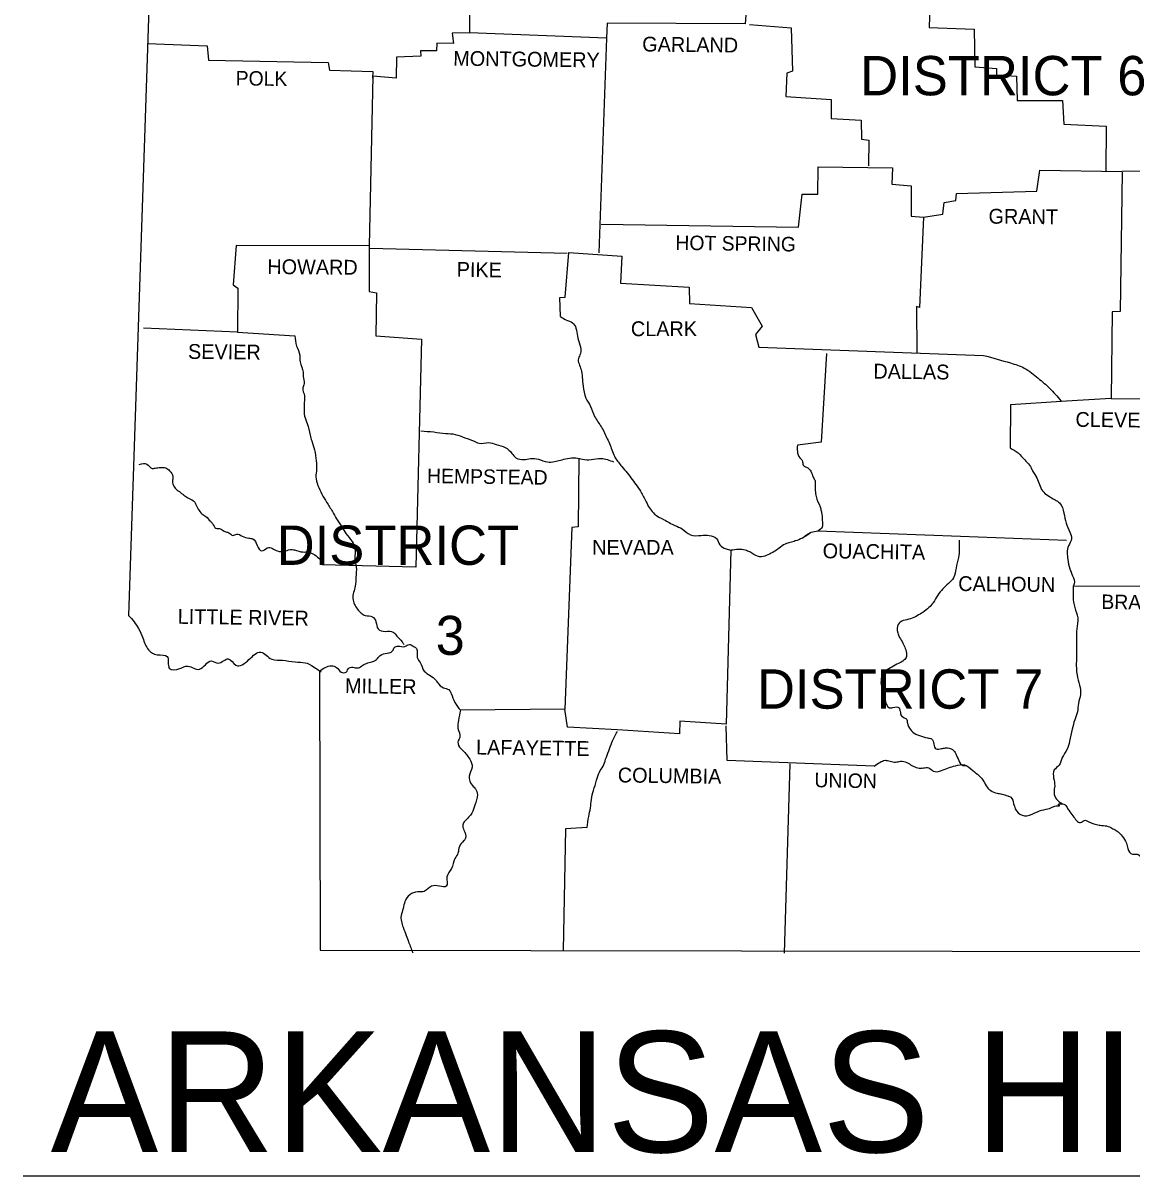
# Model space of a CAD drawing. Extents: x -33639 to 34530, y -17264 to 5867.
# Drawn here: x 1228 to 2998, y -10461 to -8621 of the extents above; entities that cross this region are included whole.
import ezdxf

# ---------------------------------------------------------------- set-up
doc = ezdxf.new("R2010")
doc.units = 0
for name, color, linetype in [('1', 7, 'Continuous'), ('2', 7, 'Continuous'), ('3', 7, 'Continuous')]:
    doc.layers.add(name, color=color, linetype=linetype)

msp = doc.modelspace()

# ---------------------------------------------------------------- linework, layer by layer
at = {"layer": '1'}
msp.add_line((1228.1, -10460.7), (4815.5, -10460.7), dxfattribs=at)
for points in [[(1332.2, -7158.5), (1446.1, -8073.2), (1396.6, -9566.3)], [(1941.4, -8314.8), (1940.3, -8636.8), (1912.8, -8637.3), (1915, -8653.9), (1888.6, -8653.3), (1888, -8665.4), (1862.2, -8665.4), (1862.7, -8674.2), (1824.2, -8675.3), (1823.6, -8708.9), (1786.2, -8705.6), (1780.2, -8976.4), (1568.3, -8975.8), (1563.3, -9038.6), (1571, -9044.1), (1570.5, -9114.5), (1420.2, -9107.9)], [(2565.5, -8557), (2385.5, -8551.5), (2380.6, -8622.5), (2160.4, -8621.4), (2159.3, -8645.1)], [(2614.5, -8555.3), (2676.1, -8559.2), (2673.9, -8628), (2746, -8630.7), (2747.1, -8690.7), (2781.2, -8693.5), (2781.2, -8703.9), (2813.2, -8706.1), (2814.3, -8744.7), (2886.9, -8744.7), (2889.1, -8782.6), (2956.3, -8785.9), (2955.7, -8857.5)], [(2387.2, -8623.6), (2453.8, -8628.5), (2456, -8697.9), (2446.6, -8701.2), (2445.5, -8738.1), (2517.6, -8743), (2517.6, -8773.3), (2565.5, -8776), (2566.1, -8806.3), (2577.6, -8808), (2577.1, -8848.7)], [(2159.3, -8645.1), (1940.3, -8636.8)], [(2159.3, -8645.1), (2146.7, -8987.9)], [(1426.8, -8653.9), (1522, -8657.2), (1524.2, -8680.3), (1714.7, -8684.1), (1716.9, -8696.2), (1786.2, -8698.4), (1785.7, -8708.9)], [(3612.3, -8794.2), (3404.2, -8788.7), (3403.1, -8856.4), (2982.1, -8858)], [(2150.5, -8942.2), (2465.3, -8946.6), (2471.4, -8894.4), (2496.2, -8894.4), (2496.7, -8850.3), (2615.6, -8852), (2614.5, -8878.4), (2645.3, -8880.6), (2645.3, -8929), (2665.1, -8930.7)], [(2665.1, -8930.7), (2695.9, -8926.3), (2698.1, -8907.6), (2716.3, -8904.3), (2717.4, -8893.3), (2845.6, -8889.4), (2850.6, -8855.8), (2982.1, -8858)], [(2982.1, -8859.1), (2978.8, -9081.5), (2966.2, -9082), (2964.5, -9220.2)], [(2665.1, -8930.7), (2658.5, -9074.9), (2653.6, -9073.2), (2654.1, -9148.1)], [(1780.2, -8976.4), (1780.2, -9049.6), (1792.3, -9051.8), (1791.2, -9120), (1863.8, -9125.5), (1855, -9489.3), (1705.3, -9485.4)], [(1781.3, -8980.2), (2096.1, -8988.5)], [(2085.6, -9089.2), (2084.5, -9058.9), (2093.3, -9058.4), (2098.8, -8987.4), (2183.6, -8992.9), (2181.4, -9036.4), (2290.9, -9042.4), (2291.4, -9068.8), (2390.5, -9074.9), (2407.6, -9104.6), (2397.1, -9117.8), (2402.1, -9138.2), (2760.9, -9151.4)], [(1570.5, -9114.5), (1661.8, -9120)], [(2509.9, -9148.6), (2501.7, -9290.1), (2463.7, -9294.5)], [(2885.3, -9225.1), (2803.8, -9230.1), (2803.3, -9298.9)], [(2964.5, -9220.2), (2884.2, -9225.1)], [(2964.5, -9220.2), (3159.3, -9221.3)], [(2114.8, -9315.4), (2113.7, -9424.9), (2103.8, -9426), (2092.8, -9716)], [(2496.2, -9431.5), (2724, -9439.8), (2893, -9446.4)], [(2357.5, -9462.3), (2350.3, -9739.7), (2276, -9734.8), (2275.5, -9755.1), (2176.4, -9749.1)], [(2904, -9519.6), (3152.7, -9519)], [(1700.9, -9655), (1702, -10100.2), (3719, -10103.5)], [(2176.4, -9749.1), (2096.6, -9744.7), (2092.8, -9716), (1926, -9717.7)], [(2586.4, -9806.9), (2351.4, -9798), (2350.3, -9742.5)], [(2451.6, -9803), (2442.8, -10105.1)], [(2128, -9904.8), (2093.9, -9907), (2090, -10100.7)]]:
    msp.add_lwpolyline(points, dxfattribs=at)
for points in [[(2085.6, -9089.2), (2094.4, -9094.7), (2104.9, -9099.6), (2110.4, -9107.9), (2112.6, -9120.6), (2116.4, -9134.3), (2117.5, -9148.6), (2114.2, -9156.3), (2118.6, -9173.9), (2120.3, -9186.1), (2121.9, -9200.4), (2126.3, -9219.6), (2133.5, -9232.8), (2140.1, -9248.8), (2151.1, -9265.9), (2160.4, -9284.6), (2164.8, -9294.5), (2173.1, -9314.8), (2183.6, -9328.6), (2200.1, -9349.5), (2214.9, -9371), (2223.2, -9386.9), (2235.8, -9404.5), (2250.2, -9413.3), (2268.3, -9422.7), (2279.9, -9428.2), (2293.1, -9437.6), (2310.1, -9438.7), (2322.8, -9438.7), (2334.4, -9443.6), (2339.9, -9453.5), (2349.8, -9460.1), (2357.5, -9462.3)], [(1661.8, -9120), (1664.6, -9136.5), (1669.5, -9150.8), (1670.1, -9161.8), (1675, -9178.3), (1675, -9184.4), (1676.7, -9196.5), (1674.5, -9203.1), (1677.2, -9216.3), (1676.7, -9226.2), (1676.7, -9234.5), (1677.2, -9248.2), (1681.6, -9260.3), (1686, -9278.5), (1688.8, -9287.9), (1693.2, -9302.2), (1695.9, -9319.8), (1696.5, -9333), (1695.4, -9345.1), (1698.7, -9358.9), (1704.8, -9372.6), (1712.5, -9385.8), (1721.8, -9400.7), (1728.4, -9412.2), (1736.7, -9424.9), (1743.3, -9435.4), (1753.2, -9448.6), (1757.6, -9459.6), (1757.6, -9475), (1759.8, -9489.3), (1759.2, -9505.3), (1758.1, -9519.6), (1754.3, -9539.4), (1757, -9548.7), (1767.5, -9562.5), (1774.1, -9566.3), (1785.7, -9568.5), (1791.2, -9576.3), (1794.5, -9587.8), (1806, -9591.7), (1818.7, -9592.8), (1824.7, -9599.4), (1833, -9608.2), (1835.7, -9612.6)], [(2760.9, -9151.4), (2803.8, -9163.5), (2825.8, -9171.7), (2847.8, -9187.7), (2866, -9203.7), (2884.2, -9224)], [(1862.7, -9271.9), (1883.6, -9273.6), (1902.9, -9275.8), (1917.7, -9277.4), (1933.2, -9282.9), (1946.9, -9287.9), (1955.7, -9291.7), (1970.6, -9290.6), (1983.2, -9293.4), (1997.5, -9298.3), (2008, -9307.7), (2014.6, -9314.8), (2027.3, -9317.6), (2037.7, -9315.9), (2050.4, -9317), (2064.7, -9321.4), (2076.2, -9320.9), (2085.6, -9318.7), (2096.6, -9315.9), (2110.4, -9314.8), (2120.8, -9317), (2134.6, -9317.6), (2150.5, -9315.9), (2170.4, -9321.4)], [(2463.7, -9294.5), (2463.7, -9304.9), (2467.5, -9314.8), (2471.4, -9319.2), (2473, -9326.4), (2478, -9329.7), (2485.2, -9336.3), (2489, -9345.7), (2491.8, -9351.7), (2491.8, -9359.4), (2492.3, -9367.1), (2493.4, -9376.5), (2500, -9393), (2501.7, -9399.6), (2502.8, -9405.1), (2503.3, -9414.4), (2503.3, -9425.5), (2496.2, -9431.5)], [(2803.3, -9298.9), (2815.9, -9307.1), (2826.4, -9318.1), (2834.1, -9326.4), (2839, -9335.7), (2845.6, -9346.8), (2855, -9367.7), (2863.2, -9374.8), (2874.8, -9382), (2882, -9386.9), (2889.1, -9402.9), (2892.4, -9418.9), (2898.5, -9433.2), (2901.2, -9444.2), (2896.3, -9455.2), (2895.2, -9477.2), (2898.5, -9492), (2902.9, -9503.1), (2905.6, -9515.7), (2904, -9519.6)], [(1413.6, -9325.3), (1425.7, -9324.7), (1434, -9331.9), (1438.9, -9331.3), (1447.7, -9330.2), (1456, -9330.8), (1462, -9335.7), (1467, -9344.6), (1466.5, -9352.8), (1467, -9356.1), (1470.9, -9363.3), (1477.5, -9368.8), (1484.6, -9374.3), (1491.2, -9378.7), (1502.2, -9385.8), (1503.3, -9388), (1507.7, -9396.8), (1513.2, -9404), (1519.8, -9408.4), (1527, -9416.1), (1530.3, -9419.4), (1535.8, -9427.1), (1541.8, -9427.7), (1550.1, -9432.6), (1556.2, -9434.3), (1562.8, -9438.7), (1569.4, -9436.5), (1577.6, -9439.8), (1588.6, -9443.1), (1594.7, -9444.2), (1601.8, -9454.6), (1609, -9463.4), (1617.8, -9458.5), (1634.3, -9463.4), (1644.8, -9464), (1654.1, -9461.2), (1661.3, -9461.8), (1674.5, -9465.1), (1682.7, -9465.1), (1691.5, -9468.4), (1699.8, -9475), (1705.3, -9482.1), (1705.3, -9485.4)], [(2485.7, -9433.7), (2471.4, -9443.1), (2460.4, -9447.5), (2452.1, -9450.2), (2444.4, -9452.4), (2434.5, -9459), (2426.8, -9464.5), (2416.4, -9469.5), (2406.5, -9472.8), (2394.3, -9468.9), (2387.7, -9465.1), (2380.6, -9462.3), (2357.5, -9462.3)], [(2471.4, -9443.1), (2485.7, -9433.7), (2496.2, -9431.5)], [(2721.8, -9446.4), (2720.7, -9473.9), (2716.9, -9490.9), (2713, -9506.4), (2704.7, -9515.2), (2695.9, -9524), (2687.7, -9533.9), (2680.5, -9546), (2673.4, -9553.7), (2664, -9561.4), (2654.7, -9566.9), (2644.2, -9571.8), (2632.7, -9574.6), (2624.4, -9580.7), (2623.8, -9593.9), (2633.2, -9612.6), (2636.5, -9621.4), (2637.6, -9631.8), (2633.8, -9637.9), (2624.9, -9642.8), (2614.5, -9648.9), (2605.1, -9654.4), (2598.5, -9663.8), (2597.4, -9676.4), (2601.8, -9691.3), (2603.5, -9700.1), (2610.6, -9713.8), (2616.1, -9713.3), (2626, -9713.8), (2627.1, -9716.6), (2627.7, -9719.3), (2629.9, -9726.5), (2638.2, -9732.6), (2639.3, -9738.1), (2644.2, -9748.5), (2652.5, -9755.7), (2658.5, -9757.9), (2671.2, -9761.7), (2677.8, -9763.4), (2684.9, -9779.3), (2693.7, -9778.8), (2700.3, -9777.7), (2711.4, -9780.4), (2716.3, -9787), (2721.3, -9798), (2727.9, -9805.8), (2732.3, -9805.8)], [(2904, -9519.6), (2906.2, -9553.7), (2911.1, -9570.2), (2909.5, -9587.8), (2908.9, -9604.9), (2908.9, -9620.3), (2908.9, -9635.1), (2908.9, -9650.6), (2910, -9661.6), (2913.9, -9677.5), (2915.5, -9692.4), (2912.2, -9706.7), (2910.6, -9719.9), (2906.2, -9733.1), (2902.3, -9748), (2897.9, -9767.2), (2894.1, -9779.9), (2886.4, -9793.1), (2881.4, -9805.2), (2873.7, -9812.9), (2872.6, -9826.1), (2874.3, -9838.2), (2873.2, -9849.2), (2877, -9859.7), (2886.9, -9866.8)], [(1396.6, -9566.3), (1412.5, -9587.3), (1419.1, -9602.1), (1428.5, -9621.4), (1442.2, -9629.1), (1458.2, -9631.8), (1461.5, -9650.6), (1478, -9651.1), (1491.2, -9647.2), (1509.4, -9652.2), (1528.6, -9639), (1539.6, -9642.3), (1555.6, -9635.7), (1567.7, -9645.6), (1588.6, -9636.8), (1607.3, -9624.7), (1625, -9636.2), (1642, -9637.9), (1662.4, -9640.6), (1678.3, -9641.7), (1692.6, -9648.9), (1703.1, -9656.1), (1700.9, -9655)], [(1700.9, -9655), (1720.2, -9646.7), (1728.4, -9649.4), (1735.6, -9656.6), (1743.8, -9656.6), (1748.2, -9650), (1756.5, -9649.4), (1763.1, -9650), (1770.2, -9645.6), (1776.3, -9642.8), (1784.6, -9640.1), (1790.6, -9637.9), (1796.1, -9631.8), (1806, -9626.9), (1817.6, -9623), (1820.9, -9617.5), (1826.4, -9615.3), (1837.4, -9615.9), (1844.5, -9612.6), (1850.6, -9615.3), (1856.1, -9619.2), (1857.2, -9633.5), (1861.6, -9641.2), (1868.2, -9655), (1877.6, -9662.1), (1886.4, -9669.3), (1889.7, -9673.7), (1899, -9681.9), (1907.3, -9684.7), (1911.1, -9690.7), (1917.2, -9705), (1926, -9717.7)], [(1926, -9717.7), (1922.7, -9733.7), (1922.1, -9746.3), (1924.9, -9761.2), (1922.1, -9768.3), (1926.5, -9778.8), (1934.8, -9787), (1940.9, -9795.8), (1944.7, -9808.5), (1939.8, -9822.8), (1945.3, -9837.7), (1950.2, -9843.2), (1953, -9852), (1949.1, -9869), (1944.2, -9881.7), (1933.2, -9894.4), (1929.8, -9900.4), (1931.5, -9908.7), (1934.3, -9921.9), (1931.5, -9925.7), (1924.3, -9935.1), (1922.1, -9945.5), (1917.2, -9954.3), (1911.7, -9970.3), (1904.5, -9983.5), (1903.4, -9998.4), (1892.4, -9998.4), (1879.8, -9998.4), (1868.2, -10006.6), (1857.8, -10007.2), (1845.1, -10012.1), (1837.4, -10022.6), (1834.6, -10034.1), (1831.3, -10045.2), (1834.6, -10063.9), (1839.6, -10077.1), (1843.4, -10087.5), (1850, -10104.6)], [(2128, -9904.8), (2130.7, -9887.2), (2133.5, -9873.4), (2135.1, -9860.2), (2138.4, -9845.4), (2143.4, -9829.4), (2147.8, -9816.2), (2153.8, -9806.9), (2157.7, -9795.8), (2162.6, -9782.6), (2167.6, -9768.9), (2176.4, -9751.3)], [(2586.4, -9806.9), (2595.2, -9800.8), (2603.5, -9797.5), (2611.7, -9799.1), (2620.5, -9800.2), (2628.2, -9799.1), (2638.2, -9800.8), (2646.4, -9805.8), (2655.8, -9809.6), (2665.1, -9809.6), (2673.4, -9809.6), (2680.5, -9814.6), (2693.7, -9814), (2704.7, -9809.6), (2715.8, -9806.3), (2730.6, -9804.6), (2743.8, -9814), (2753.2, -9821.7), (2760.9, -9830.5), (2766.4, -9840.4), (2772.4, -9845.9), (2782.3, -9849.8), (2790.1, -9851.4), (2799.4, -9854.2), (2804.4, -9856.4), (2808.8, -9866.8), (2815.9, -9881.1), (2829.7, -9886.1), (2846.7, -9879.5), (2860.5, -9875.6), (2870.4, -9872.3), (2876.5, -9870.1), (2882, -9869.6), (2880.3, -9868.5), (2886.9, -9866.8), (2893, -9871.2), (2896.8, -9877.3), (2903.4, -9886.1), (2909.5, -9893.8), (2915.5, -9896.6), (2921.6, -9893.3), (2929.8, -9896), (2937, -9898.8), (2945.3, -9901), (2952.4, -9901.5), (2961.8, -9903.7), (2968.9, -9907.6), (2975.5, -9911.4), (2982.1, -9918.6), (2988.7, -9929.6), (2990.9, -9938.4), (2998.6, -9947.2), (3005.8, -9947.2), (3016.2, -9961.5), (3020.1, -9967), (3028.4, -9976.9), (3034.4, -9976.9), (3046, -9979.1)]]:
    msp.add_spline(points, degree=3, dxfattribs=at)

# ---------------------------------------------------------------- texts
at = {"layer": '2'}
for s, height, rotation, p in [('GARLAND', 23.67, 359.3658, (2216, -8666.5)), ('MONTGOMERY', 23.67, 359.2944, (1914.4, -8689.1)), ('POLK', 23.11, 359.2152, (1567.2, -8720.5)), ('GRANT', 23.67, 359.4032, (2768.6, -8941.1)), ('HOT SPRING', 23.11, 359.2216, (2268.9, -8983)), ('HOWARD', 23.67, 359.5145, (1617.8, -9021.5)), ('PIKE', 23.66, 359.0452, (1919.9, -9025.9)), ('SEVIER', 23.67, 359.4271, (1491.2, -9156.9)), ('DALLAS', 23.66, 359.2462, (2584.8, -9188.3)), ('CLEVELAND', 23.67, 359.3377, (2907.3, -9265.3)), ('HEMPSTEAD', 23.11, 359.1885, (1872.6, -9355)), ('OUACHITA', 23.67, 359.2043, (2503.9, -9475)), ('CALHOUN', 23.67, 359.3634, (2720.2, -9527.3)), ('BRADLEY', 23.11, 359.1449, (2948.6, -9555.9)), ('LITTLE RIVER', 23.666, 359.1697, (1474.7, -9579.6)), ('MILLER', 23.66, 359.1319, (1741.6, -9690.2)), ('LAFAYETTE', 23.66, 359.1839, (1950.8, -9788.1)), ('COLUMBIA', 23.66, 359.2125, (2177, -9832.7)), ('UNION', 23.11, 358.9584, (2490.7, -9840.4))]:
    msp.add_text(s, height=height, rotation=rotation, dxfattribs=at).set_placement(p)
for s, height, p in [('CLARK', 23.67, (2198, -9120.7)), ('NEVADA', 23.67, (2136.2, -9469.5)), ('ARKANSAS HIGHWAY DISTRICT 1', 192.623, (1272.1, -10422.7))]:
    msp.add_text(s, height=height, dxfattribs=at).set_placement(p)
at = {"layer": '3'}
for s, height, p in [('DISTRICT 6', 62.74, (2563.9, -8736.4)), ('DISTRICT', 62.74, (1632.8, -9485.6)), ('3', 62.2, (1886.6, -9629.2)), ('DISTRICT 7', 62.74, (2399.2, -9715.1))]:
    msp.add_text(s, height=height, dxfattribs=at).set_placement(p)

doc.saveas('drawing.dxf')
